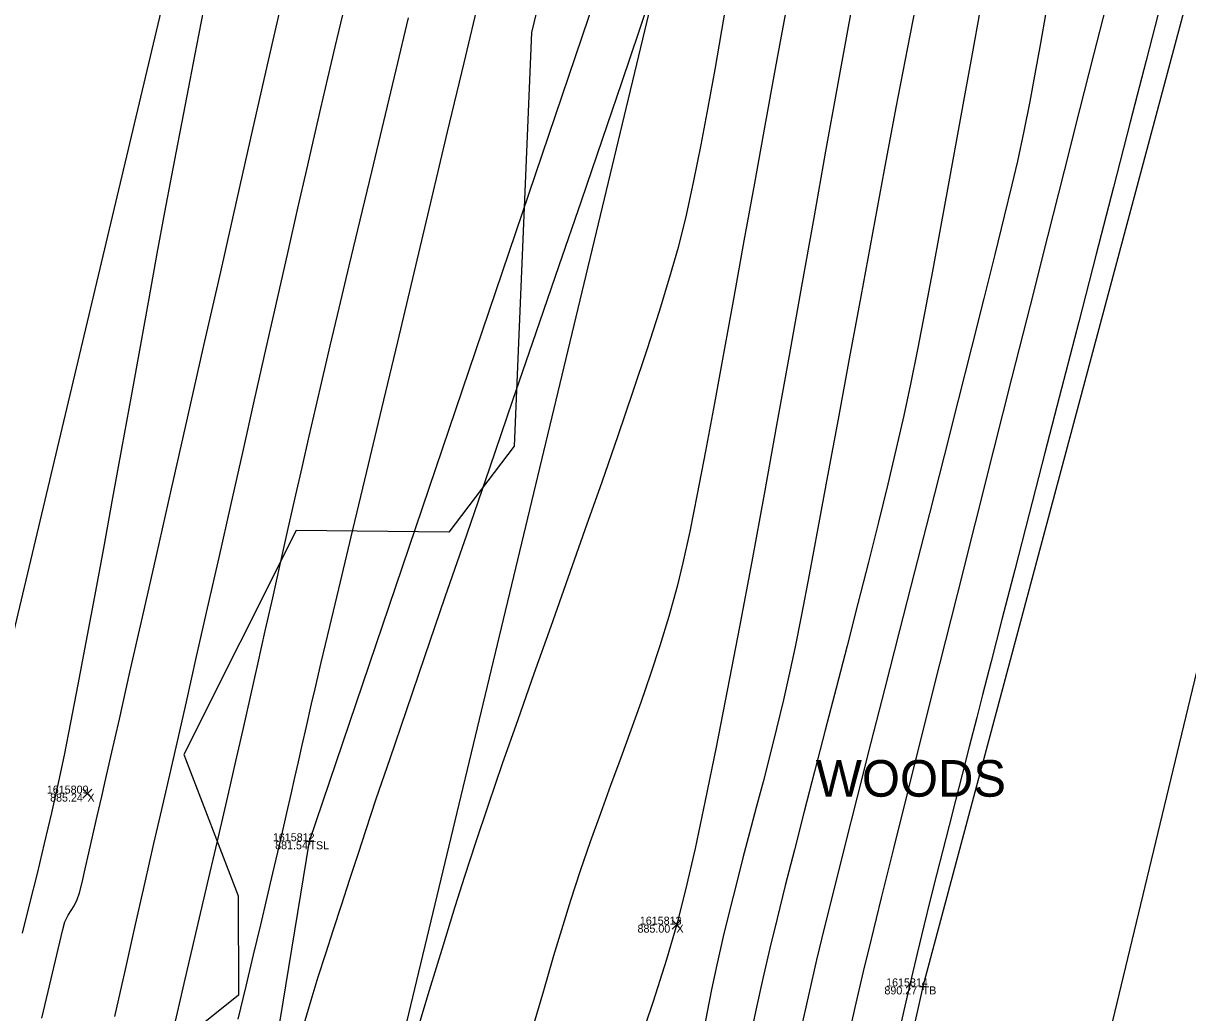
# Model space of a CAD drawing. Extents: x 1957117 to 1971063, y 701601 to 715861.
# Drawn here: x 1962959.5 to 1963010.4, y 704725.9 to 704769.1 of the extents above; entities that cross this region are included whole.
import ezdxf

# ---------------------------------------------------------------- set-up
doc = ezdxf.new("R2010")
doc.units = 0
for name, color, linetype in [('AP_X_Lights', 7, 'Continuous'), ('DT_X_Break_Line', 7, 'Continuous'), ('DT_X_Contour_Major', 7, 'Continuous'), ('DT_X_Contour_Minor', 7, 'Continuous'), ('DT_X_TIN_Hull', 7, 'Continuous'), ('GE_X_CL_20', 7, 'Continuous'), ('HY_X_Water_Edge', 7, 'Continuous'), ('PV_P_Drive', 7, 'Continuous'), ('PV_P_Shoulder', 7, 'Continuous'), ('RS_Raster1', 7, 'Continuous'), ('RW_X_Esmt_RR', 7, 'Continuous'), ('SC_Scratch1', 7, 'Continuous'), ('VG_X_Text', 7, 'Continuous'), ('VG_X_Tree_Line_Rt', 7, 'Continuous')]:
    doc.layers.add(name, color=color, linetype=linetype)

msp = doc.modelspace()

# ---------------------------------------------------------------- linework, layer by layer
at = {"layer": 'AP_X_Lights'}
for p, q in [((1962962.134, 704735.237), (1962962.522, 704735.627)), ((1962962.134, 704735.627), (1962962.522, 704735.237)), ((1962987.896, 704729.509), (1962988.284, 704729.899)), ((1962987.896, 704729.899), (1962988.284, 704729.509))]:
    msp.add_line(p, q, dxfattribs=at)
at = {"layer": 'DT_X_Break_Line'}
for points in [[(1962854.549, 704243.654), (1962868.069, 704295.231), (1962879.669, 704344.313), (1962892.757, 704392.318), (1962905.964, 704443.142), (1962917.718, 704492.375), (1962926.962, 704538.336), (1962936.778, 704587.265), (1962949.215, 704630.669), (1962963.968, 704683.754), (1962972.038, 704733.348), (1962988.206, 704780.999), (1962994.689, 704830.943), (1963004.932, 704879.138), (1963021.822, 704927.498), (1963031.944, 704976.286), (1963045.21, 705027.355), (1963059.618, 705072.384), (1963067.267, 705121.949)], [(1963081.686, 705067.168), (1963070.617, 705018.992), (1963060.629, 704969.66), (1963044.793, 704921.859), (1963033.624, 704869.219), (1963022.038, 704824.561), (1963012.554, 704778.141), (1962998.858, 704727.004), (1962987.967, 704677.611), (1962975.675, 704626.305), (1962966.447, 704580.213), (1962950.262, 704533.092), (1962939.515, 704481.257), (1962926.044, 704436.037), (1962917.68, 704386.811), (1962906.11, 704337.415), (1962892.064, 704289.931), (1962881.011, 704234.451)]]:
    msp.add_lwpolyline(points, dxfattribs=at)
at = {"layer": 'DT_X_Contour_Major'}
for points in [[(1962996.058, 704771.404), (1962995.601, 704768.948), (1962995.119, 704766.305), (1962994.614, 704763.511), (1962994.093, 704760.601), (1962993.558, 704757.611), (1962993.015, 704754.578), (1962992.468, 704751.537), (1962991.922, 704748.523), (1962991.38, 704745.574), (1962990.848, 704742.724), (1962990.329, 704740.01), (1962989.829, 704737.467), (1962989.352, 704735.131), (1962988.901, 704733.039), (1962988.483, 704731.225), (1962988.1, 704729.726), (1962987.648, 704728.176), (1962987.068, 704726.348), (1962986.373, 704724.273)], [(1962996.058, 704771.404), (1962995.601, 704768.948), (1962995.119, 704766.305), (1962994.614, 704763.511), (1962994.093, 704760.601), (1962993.558, 704757.611), (1962993.015, 704754.578), (1962992.468, 704751.537), (1962991.922, 704748.523), (1962991.38, 704745.574), (1962990.848, 704742.724), (1962990.329, 704740.01), (1962989.829, 704737.467), (1962989.352, 704735.131), (1962988.901, 704733.039), (1962988.483, 704731.225), (1962988.1, 704729.726), (1962987.648, 704728.176), (1962987.068, 704726.348), (1962986.373, 704724.273)], [(1962960.331, 704725.618), (1962960.736, 704727.33), (1962961.048, 704728.638), (1962961.256, 704729.491), (1962961.346, 704729.834), (1962961.48, 704730.115), (1962961.615, 704730.321), (1962961.751, 704730.528), (1962961.885, 704730.808), (1962961.975, 704731.096), (1962962.093, 704731.549), (1962962.233, 704732.138), (1962962.393, 704732.837), (1962962.569, 704733.615), (1962962.757, 704734.445), (1962962.953, 704735.298), (1962963.092, 704735.906), (1962963.354, 704737.058), (1962963.725, 704738.69), (1962964.19, 704740.739), (1962964.735, 704743.141), (1962965.346, 704745.834), (1962966.007, 704748.753), (1962966.706, 704751.836), (1962967.427, 704755.019), (1962968.157, 704758.238), (1962968.881, 704761.431), (1962969.584, 704764.534), (1962970.253, 704767.483), (1962970.872, 704770.216)], [(1962960.331, 704725.618), (1962960.736, 704727.33), (1962961.048, 704728.638), (1962961.256, 704729.491), (1962961.346, 704729.834), (1962961.48, 704730.115), (1962961.615, 704730.321), (1962961.751, 704730.528), (1962961.885, 704730.808), (1962961.975, 704731.096), (1962962.093, 704731.549), (1962962.233, 704732.138), (1962962.393, 704732.837), (1962962.569, 704733.615), (1962962.757, 704734.445), (1962962.953, 704735.298), (1962963.092, 704735.906), (1962963.354, 704737.058), (1962963.725, 704738.69), (1962964.19, 704740.739), (1962964.735, 704743.141), (1962965.346, 704745.834), (1962966.007, 704748.753), (1962966.706, 704751.836), (1962967.427, 704755.019), (1962968.157, 704758.238), (1962968.881, 704761.431), (1962969.584, 704764.534), (1962970.253, 704767.483), (1962970.872, 704770.216)], [(1963009.269, 704769.969), (1963008.626, 704767.475), (1963007.93, 704764.777), (1963007.197, 704761.935), (1963006.442, 704759.01), (1963005.681, 704756.06), (1963004.929, 704753.146), (1963004.202, 704750.327), (1963003.516, 704747.664), (1963002.885, 704745.215), (1963002.325, 704743.04), (1963001.851, 704741.2), (1963001.48, 704739.754), (1963001.226, 704738.762), (1963000.897, 704737.471), (1963000.588, 704736.267), (1963000.295, 704735.128), (1963000.013, 704734.033), (1962999.738, 704732.959), (1962999.466, 704731.884), (1962999.191, 704730.787), (1962998.908, 704729.646), (1962998.615, 704728.438), (1962998.305, 704727.143), (1962998.074, 704726.146), (1962997.727, 704724.617)], [(1963009.269, 704769.969), (1963008.626, 704767.475), (1963007.93, 704764.777), (1963007.197, 704761.935), (1963006.442, 704759.01), (1963005.681, 704756.06), (1963004.929, 704753.146), (1963004.202, 704750.327), (1963003.516, 704747.664), (1963002.885, 704745.215), (1963002.325, 704743.04), (1963001.851, 704741.2), (1963001.48, 704739.754), (1963001.226, 704738.762), (1963000.897, 704737.471), (1963000.588, 704736.267), (1963000.295, 704735.128), (1963000.013, 704734.033), (1962999.738, 704732.959), (1962999.466, 704731.884), (1962999.191, 704730.787), (1962998.908, 704729.646), (1962998.615, 704728.438), (1962998.305, 704727.143), (1962998.074, 704726.146), (1962997.727, 704724.617)], [(1962967.404, 704769.702), (1962967.098, 704768.133), (1962966.805, 704766.619), (1962966.525, 704765.174), (1962966.262, 704763.813), (1962966.002, 704762.451), (1962965.703, 704760.848), (1962965.371, 704759.042), (1962965.011, 704757.073), (1962964.631, 704754.981), (1962964.236, 704752.805), (1962963.833, 704750.584), (1962963.428, 704748.358), (1962963.027, 704746.167), (1962962.636, 704744.05), (1962962.262, 704742.046), (1962961.912, 704740.195), (1962961.59, 704738.536), (1962961.305, 704737.109), (1962961.061, 704735.954), (1962960.756, 704734.594), (1962960.444, 704733.258), (1962960.125, 704731.939), (1962959.8, 704730.634), (1962959.47, 704729.338)], [(1962967.404, 704769.702), (1962967.098, 704768.133), (1962966.805, 704766.619), (1962966.525, 704765.174), (1962966.262, 704763.813), (1962966.002, 704762.451), (1962965.703, 704760.848), (1962965.371, 704759.042), (1962965.011, 704757.073), (1962964.631, 704754.981), (1962964.236, 704752.805), (1962963.833, 704750.584), (1962963.428, 704748.358), (1962963.027, 704746.167), (1962962.636, 704744.05), (1962962.262, 704742.046), (1962961.912, 704740.195), (1962961.59, 704738.536), (1962961.305, 704737.109), (1962961.061, 704735.954), (1962960.756, 704734.594), (1962960.444, 704733.258), (1962960.125, 704731.939), (1962959.8, 704730.634), (1962959.47, 704729.338)]]:
    msp.add_lwpolyline(points, dxfattribs=at)
at = {"layer": 'DT_X_Contour_Minor'}
for points in [[(1962987.088, 704770.672), (1962986.44, 704768.74), (1962985.683, 704766.505), (1962984.836, 704764.018), (1962983.918, 704761.333), (1962982.948, 704758.502), (1962981.944, 704755.578), (1962980.924, 704752.615), (1962979.909, 704749.664), (1962978.916, 704746.779), (1962977.965, 704744.012), (1962977.074, 704741.417), (1962976.262, 704739.046), (1962975.547, 704736.952), (1962974.949, 704735.189), (1962974.486, 704733.808), (1962974.177, 704732.862), (1962973.796, 704731.673), (1962973.43, 704730.547), (1962973.078, 704729.47), (1962972.739, 704728.427), (1962972.412, 704727.404), (1962972.095, 704726.385), (1962971.788, 704725.357)], [(1962987.088, 704770.672), (1962986.44, 704768.74), (1962985.683, 704766.505), (1962984.836, 704764.018), (1962983.918, 704761.333), (1962982.948, 704758.502), (1962981.944, 704755.578), (1962980.924, 704752.615), (1962979.909, 704749.664), (1962978.916, 704746.779), (1962977.965, 704744.012), (1962977.074, 704741.417), (1962976.262, 704739.046), (1962975.547, 704736.952), (1962974.949, 704735.189), (1962974.486, 704733.808), (1962974.177, 704732.862), (1962973.796, 704731.673), (1962973.43, 704730.547), (1962973.078, 704729.47), (1962972.739, 704728.427), (1962972.412, 704727.404), (1962972.095, 704726.385), (1962971.788, 704725.357)], [(1962990.344, 704770.487), (1962990.056, 704768.783), (1962989.765, 704767.087), (1962989.467, 704765.416), (1962989.161, 704763.786), (1962988.842, 704762.212), (1962988.508, 704760.711), (1962988.157, 704759.299), (1962987.792, 704758.005), (1962987.334, 704756.506), (1962986.794, 704754.83), (1962986.186, 704753.008), (1962985.524, 704751.069), (1962984.82, 704749.043), (1962984.088, 704746.961), (1962983.342, 704744.85), (1962982.594, 704742.742), (1962981.858, 704740.666), (1962981.147, 704738.652), (1962980.474, 704736.73), (1962979.853, 704734.929), (1962979.296, 704733.278), (1962978.818, 704731.809), (1962978.4, 704730.479), (1962977.882, 704728.803), (1962977.277, 704726.828), (1962976.6, 704724.602)], [(1962990.344, 704770.487), (1962990.056, 704768.783), (1962989.765, 704767.087), (1962989.467, 704765.416), (1962989.161, 704763.786), (1962988.842, 704762.212), (1962988.508, 704760.711), (1962988.157, 704759.299), (1962987.792, 704758.005), (1962987.334, 704756.506), (1962986.794, 704754.83), (1962986.186, 704753.008), (1962985.524, 704751.069), (1962984.82, 704749.043), (1962984.088, 704746.961), (1962983.342, 704744.85), (1962982.594, 704742.742), (1962981.858, 704740.666), (1962981.147, 704738.652), (1962980.474, 704736.73), (1962979.853, 704734.929), (1962979.296, 704733.278), (1962978.818, 704731.809), (1962978.4, 704730.479), (1962977.882, 704728.803), (1962977.277, 704726.828), (1962976.6, 704724.602)], [(1962998.668, 704770.525), (1962998.19, 704768.05), (1962997.69, 704765.426), (1962997.178, 704762.703), (1962996.661, 704759.93), (1962996.146, 704757.156), (1962995.643, 704754.431), (1962995.157, 704751.803), (1962994.698, 704749.322), (1962994.273, 704747.038), (1962993.889, 704744.998), (1962993.555, 704743.253), (1962993.278, 704741.851), (1962993.066, 704740.842), (1962992.766, 704739.528), (1962992.468, 704738.283), (1962992.171, 704737.092), (1962991.876, 704735.944), (1962991.582, 704734.824), (1962991.289, 704733.72), (1962990.998, 704732.618), (1962990.709, 704731.504), (1962990.422, 704730.367), (1962990.136, 704729.191), (1962989.853, 704727.95), (1962989.624, 704726.864), (1962989.431, 704725.888), (1962989.258, 704724.98)], [(1962998.668, 704770.525), (1962998.19, 704768.05), (1962997.69, 704765.426), (1962997.178, 704762.703), (1962996.661, 704759.93), (1962996.146, 704757.156), (1962995.643, 704754.431), (1962995.157, 704751.803), (1962994.698, 704749.322), (1962994.273, 704747.038), (1962993.889, 704744.998), (1962993.555, 704743.253), (1962993.278, 704741.851), (1962993.066, 704740.842), (1962992.766, 704739.528), (1962992.468, 704738.283), (1962992.171, 704737.092), (1962991.876, 704735.944), (1962991.582, 704734.824), (1962991.289, 704733.72), (1962990.998, 704732.618), (1962990.709, 704731.504), (1962990.422, 704730.367), (1962990.136, 704729.191), (1962989.853, 704727.95), (1962989.624, 704726.864), (1962989.431, 704725.888), (1962989.258, 704724.98)], [(1962968.928, 704725.578), (1962969.269, 704727.012), (1962969.597, 704728.391), (1962969.906, 704729.693), (1962970.189, 704730.89), (1962970.441, 704731.959), (1962970.656, 704732.873), (1962970.828, 704733.608), (1962971.055, 704734.594), (1962971.242, 704735.414), (1962971.403, 704736.135), (1962971.556, 704736.823), (1962971.717, 704737.543), (1962971.904, 704738.364), (1962972.131, 704739.35), (1962972.287, 704740.012), (1962972.558, 704741.158), (1962972.933, 704742.734), (1962973.397, 704744.687), (1962973.939, 704746.961), (1962974.545, 704749.504), (1962975.202, 704752.26), (1962975.897, 704755.177), (1962976.618, 704758.201), (1962977.35, 704761.276), (1962978.082, 704764.351), (1962978.801, 704767.369), (1962979.493, 704770.278)], [(1962968.928, 704725.578), (1962969.269, 704727.012), (1962969.597, 704728.391), (1962969.906, 704729.693), (1962970.189, 704730.89), (1962970.441, 704731.959), (1962970.656, 704732.873), (1962970.828, 704733.608), (1962971.055, 704734.594), (1962971.242, 704735.414), (1962971.403, 704736.135), (1962971.556, 704736.823), (1962971.717, 704737.543), (1962971.904, 704738.364), (1962972.131, 704739.35), (1962972.287, 704740.012), (1962972.558, 704741.158), (1962972.933, 704742.734), (1962973.397, 704744.687), (1962973.939, 704746.961), (1962974.545, 704749.504), (1962975.202, 704752.26), (1962975.897, 704755.177), (1962976.618, 704758.201), (1962977.35, 704761.276), (1962978.082, 704764.351), (1962978.801, 704767.369), (1962979.493, 704770.278)], [(1962963.529, 704725.692), (1962963.99, 704727.737), (1962964.434, 704729.708), (1962964.853, 704731.562), (1962965.237, 704733.252), (1962965.578, 704734.735), (1962965.885, 704736.066), (1962966.248, 704737.648), (1962966.657, 704739.444), (1962967.105, 704741.418), (1962967.583, 704743.531), (1962968.084, 704745.747), (1962968.599, 704748.029), (1962969.121, 704750.339), (1962969.64, 704752.64), (1962970.149, 704754.896), (1962970.64, 704757.069), (1962971.104, 704759.121), (1962971.534, 704761.017), (1962971.921, 704762.718), (1962972.257, 704764.188), (1962972.534, 704765.389), (1962972.843, 704766.71), (1962973.164, 704768.073), (1962973.496, 704769.469)], [(1962963.529, 704725.692), (1962963.99, 704727.737), (1962964.434, 704729.708), (1962964.853, 704731.562), (1962965.237, 704733.252), (1962965.578, 704734.735), (1962965.885, 704736.066), (1962966.248, 704737.648), (1962966.657, 704739.444), (1962967.105, 704741.418), (1962967.583, 704743.531), (1962968.084, 704745.747), (1962968.599, 704748.029), (1962969.121, 704750.339), (1962969.64, 704752.64), (1962970.149, 704754.896), (1962970.64, 704757.069), (1962971.104, 704759.121), (1962971.534, 704761.017), (1962971.921, 704762.718), (1962972.257, 704764.188), (1962972.534, 704765.389), (1962972.843, 704766.71), (1962973.164, 704768.073), (1962973.496, 704769.469)], [(1962966.023, 704724.792), (1962966.61, 704727.314), (1962967.134, 704729.568), (1962967.582, 704731.498), (1962967.943, 704733.051), (1962968.203, 704734.171), (1962968.507, 704735.489), (1962968.819, 704736.848), (1962969.135, 704738.24), (1962969.456, 704739.659), (1962969.779, 704741.096), (1962970.105, 704742.544), (1962970.431, 704743.996), (1962970.756, 704745.445), (1962971.08, 704746.882), (1962971.401, 704748.301), (1962971.717, 704749.693), (1962972.028, 704751.052), (1962972.333, 704752.37), (1962972.611, 704753.558), (1962972.951, 704754.998), (1962973.344, 704756.657), (1962973.783, 704758.501), (1962974.26, 704760.497), (1962974.765, 704762.611), (1962975.292, 704764.812), (1962975.831, 704767.066), (1962976.375, 704769.339)], [(1962966.023, 704724.792), (1962966.61, 704727.314), (1962967.134, 704729.568), (1962967.582, 704731.498), (1962967.943, 704733.051), (1962968.203, 704734.171), (1962968.507, 704735.489), (1962968.819, 704736.848), (1962969.135, 704738.24), (1962969.456, 704739.659), (1962969.779, 704741.096), (1962970.105, 704742.544), (1962970.431, 704743.996), (1962970.756, 704745.445), (1962971.08, 704746.882), (1962971.401, 704748.301), (1962971.717, 704749.693), (1962972.028, 704751.052), (1962972.333, 704752.37), (1962972.611, 704753.558), (1962972.951, 704754.998), (1962973.344, 704756.657), (1962973.783, 704758.501), (1962974.26, 704760.497), (1962974.765, 704762.611), (1962975.292, 704764.812), (1962975.831, 704767.066), (1962976.375, 704769.339)], [(1962992.856, 704769.56), (1962992.407, 704767.131), (1962991.952, 704764.635), (1962991.496, 704762.11), (1962991.043, 704759.594), (1962990.598, 704757.127), (1962990.167, 704754.747), (1962989.753, 704752.494), (1962989.363, 704750.407), (1962988.999, 704748.523), (1962988.669, 704746.883), (1962988.375, 704745.524), (1962988.123, 704744.487), (1962987.757, 704743.172), (1962987.368, 704741.895), (1962986.96, 704740.646), (1962986.536, 704739.418), (1962986.101, 704738.204), (1962985.659, 704736.995), (1962985.212, 704735.783), (1962984.765, 704734.561), (1962984.321, 704733.321), (1962983.884, 704732.055), (1962983.459, 704730.755), (1962983.119, 704729.661), (1962982.719, 704728.336), (1962982.269, 704726.815), (1962981.776, 704725.13)], [(1962992.856, 704769.56), (1962992.407, 704767.131), (1962991.952, 704764.635), (1962991.496, 704762.11), (1962991.043, 704759.594), (1962990.598, 704757.127), (1962990.167, 704754.747), (1962989.753, 704752.494), (1962989.363, 704750.407), (1962988.999, 704748.523), (1962988.669, 704746.883), (1962988.375, 704745.524), (1962988.123, 704744.487), (1962987.757, 704743.172), (1962987.368, 704741.895), (1962986.96, 704740.646), (1962986.536, 704739.418), (1962986.101, 704738.204), (1962985.659, 704736.995), (1962985.212, 704735.783), (1962984.765, 704734.561), (1962984.321, 704733.321), (1962983.884, 704732.055), (1962983.459, 704730.755), (1962983.119, 704729.661), (1962982.719, 704728.336), (1962982.269, 704726.815), (1962981.776, 704725.13)], [(1963001.359, 704769.632), (1963001.016, 704767.773), (1963000.669, 704765.865), (1963000.319, 704763.934), (1962999.971, 704762.006), (1962999.625, 704760.107), (1962999.285, 704758.263), (1962998.953, 704756.5), (1962998.632, 704754.844), (1962998.324, 704753.322), (1962998.032, 704751.959), (1962997.705, 704750.522), (1962997.333, 704748.958), (1962996.925, 704747.291), (1962996.488, 704745.544), (1962996.029, 704743.738), (1962995.556, 704741.898), (1962995.078, 704740.047), (1962994.6, 704738.206), (1962994.131, 704736.399), (1962993.678, 704734.649), (1962993.249, 704732.98), (1962992.851, 704731.413), (1962992.491, 704729.971), (1962992.178, 704728.679), (1962991.871, 704727.348), (1962991.568, 704725.967), (1962991.268, 704724.547)], [(1963001.359, 704769.632), (1963001.016, 704767.773), (1963000.669, 704765.865), (1963000.319, 704763.934), (1962999.971, 704762.006), (1962999.625, 704760.107), (1962999.285, 704758.263), (1962998.953, 704756.5), (1962998.632, 704754.844), (1962998.324, 704753.322), (1962998.032, 704751.959), (1962997.705, 704750.522), (1962997.333, 704748.958), (1962996.925, 704747.291), (1962996.488, 704745.544), (1962996.029, 704743.738), (1962995.556, 704741.898), (1962995.078, 704740.047), (1962994.6, 704738.206), (1962994.131, 704736.399), (1962993.678, 704734.649), (1962993.249, 704732.98), (1962992.851, 704731.413), (1962992.491, 704729.971), (1962992.178, 704728.679), (1962991.871, 704727.348), (1962991.568, 704725.967), (1962991.268, 704724.547)], [(1963004.224, 704769.486), (1963004.005, 704768.234), (1963003.777, 704766.966), (1963003.537, 704765.683), (1963003.279, 704764.385), (1963002.999, 704763.075), (1963002.76, 704762.04), (1963002.428, 704760.666), (1963002.017, 704758.996), (1963001.536, 704757.072), (1963000.997, 704754.936), (1963000.412, 704752.631), (1962999.793, 704750.199), (1962999.15, 704747.682), (1962998.496, 704745.122), (1962997.841, 704742.561), (1962997.198, 704740.042), (1962996.577, 704737.606), (1962995.991, 704735.297), (1962995.451, 704733.157), (1962994.968, 704731.227), (1962994.554, 704729.549), (1962994.22, 704728.167), (1962993.876, 704726.681), (1962993.504, 704725.01)], [(1963004.224, 704769.486), (1963004.005, 704768.234), (1963003.777, 704766.966), (1963003.537, 704765.683), (1963003.279, 704764.385), (1963002.999, 704763.075), (1963002.76, 704762.04), (1963002.428, 704760.666), (1963002.017, 704758.996), (1963001.536, 704757.072), (1963000.997, 704754.936), (1963000.412, 704752.631), (1962999.793, 704750.199), (1962999.15, 704747.682), (1962998.496, 704745.122), (1962997.841, 704742.561), (1962997.198, 704740.042), (1962996.577, 704737.606), (1962995.991, 704735.297), (1962995.451, 704733.157), (1962994.968, 704731.227), (1962994.554, 704729.549), (1962994.22, 704728.167), (1962993.876, 704726.681), (1962993.504, 704725.01)], [(1963006.865, 704769.826), (1963006.332, 704767.722), (1963005.721, 704765.314), (1963005.046, 704762.65), (1963004.319, 704759.782), (1963003.553, 704756.76), (1963002.761, 704753.633), (1963001.957, 704750.452), (1963001.152, 704747.267), (1963000.36, 704744.128), (1962999.594, 704741.085), (1962998.867, 704738.189), (1962998.191, 704735.489), (1962997.58, 704733.035), (1962997.046, 704730.878), (1962996.603, 704729.068), (1962996.262, 704727.655), (1962995.896, 704726.08), (1962995.472, 704724.206)], [(1963006.865, 704769.826), (1963006.332, 704767.722), (1963005.721, 704765.314), (1963005.046, 704762.65), (1963004.319, 704759.782), (1963003.553, 704756.76), (1963002.761, 704753.633), (1963001.957, 704750.452), (1963001.152, 704747.267), (1963000.36, 704744.128), (1962999.594, 704741.085), (1962998.867, 704738.189), (1962998.191, 704735.489), (1962997.58, 704733.035), (1962997.046, 704730.878), (1962996.603, 704729.068), (1962996.262, 704727.655), (1962995.896, 704726.08), (1962995.472, 704724.206)]]:
    msp.add_lwpolyline(points, dxfattribs=at)
at = {"layer": 'DT_X_TIN_Hull'}
msp.add_lwpolyline([(1963062.2, 705175.46), (1963037.999, 705077.244), (1963026.56, 705028.621), (1963015.244, 704980.352), (1962992.578, 704882.771), (1962981.085, 704833.91), (1962969.384, 704785.804), (1962957.851, 704737.276), (1962945.67, 704688.173), (1962933.954, 704639.432), (1962922.363, 704591.169), (1962899.093, 704494.258), (1962887.945, 704444.945), (1962875.826, 704396.455), (1962864.548, 704347.909), (1962854.544, 704302.816), (1962839.463, 704247.251)], dxfattribs=at)
at = {"layer": 'GE_X_CL_20'}
msp.add_lwpolyline([(1963418.3, 706437.397), (1962895.621, 704261.062)], dxfattribs=at)
at = {"layer": 'HY_X_Water_Edge'}
msp.add_spline([(1963191.723, 701994.048), (1963062.047, 702441.167), (1962863.491, 703169.356), (1962827.53, 703438.691), (1962823.213, 703537.412), (1962817.962, 703593.874), (1962817.97, 703697.316), (1962828.582, 703804.235), (1962836.461, 703844.734), (1962850.687, 703896.004), (1962867.251, 703938.846), (1962873.848, 703992.355), (1962884.135, 704091.371), (1962891.241, 704140.854), (1962897.382, 704180.529), (1962905.467, 704230.979), (1962943.949, 704328.022), (1962948.537, 704378.842), (1962964.114, 704426.264), (1963004.885, 704570.73), (1963042.054, 704716.522), (1963062.038, 704814.417), (1963072.171, 704860.237), (1963090.023, 704956.798), (1963107.066, 705031.783), (1963133.773, 705105.742), (1963148.685, 705206.74), (1963175.48, 705301.059), (1963191.635, 705353.417), (1963210.988, 705447.286), (1963219.532, 705497.27), (1963230.124, 705549.475), (1963251.052, 705591.159), (1963275.289, 705693.429), (1963292.982, 705784.032), (1963302.841, 705839.645), (1963335.126, 705936.766), (1963359.752, 706046.75), (1963389.133, 706177.299), (1963417.827, 706273.456), (1963475.868, 706451.902), (1963533.782, 706640.53), (1963553.86, 706696.984), (1963580.184, 706715.425), (1963609.172, 706718.73), (1963617.062, 706714.691), (1963619.447, 706694.678), (1963564.282, 706533.07), (1963531.853, 706395.229), (1963434.4, 706006.96), (1963354.09, 705679.186), (1963237.513, 705206.07), (1963167.369, 704892.962), (1963059.145, 704434.176), (1962907.914, 703908.742), (1962877.458, 703703.326), (1962898.357, 703412.121), (1962942.65, 703052.267), (1963048.963, 702674.866), (1963191.468, 702189.666), (1963245.396, 702019.832)], degree=3, dxfattribs=at)
at = {"layer": 'PV_P_Drive'}
for p, q in [((1962971.892, 704733.348), (1962972.184, 704733.348)), ((1962972.038, 704733.494), (1962972.038, 704733.202)), ((1962972.038, 704733.348), (1962972.038, 704733.348)), ((1962998.858, 704727.15), (1962998.858, 704726.858)), ((1962998.712, 704727.004), (1962999.004, 704727.004)), ((1962998.858, 704727.004), (1962998.858, 704727.004))]:
    msp.add_line(p, q, dxfattribs=at)
at = {"layer": 'RW_X_Esmt_RR'}
msp.add_lwpolyline([(1962866.45, 704268.068), (1963123.345, 705337.727), (1963135.496, 705336.937), (1963400.797, 706441.601)], dxfattribs=at)
at = {"layer": 'VG_X_Tree_Line_Rt'}
msp.add_lwpolyline([(1962986.237, 704787.296), (1962981.745, 704768.701), (1962980.999, 704750.624), (1962978.13, 704746.854), (1962971.461, 704746.926), (1962966.551, 704737.148), (1962968.927, 704730.966), (1962968.939, 704726.627), (1962964.184, 704722.821), (1962959.744, 704715.96), (1962961.918, 704707.89), (1962967.024, 704704.665), (1962971.423, 704700.785), (1962967.465, 704693.674), (1962959.916, 704673.133)], dxfattribs=at)

# ---------------------------------------------------------------- texts
at = {"layer": 'PV_P_Shoulder'}
for s, p in [('885.24', (1962960.697, 704735.082)), ('881.54', (1962970.539, 704732.998)), ('885.00', (1962986.387, 704729.354)), ('890.27', (1962997.185, 704726.654))]:
    msp.add_text(s, height=0.35, dxfattribs=at).set_placement(p)
at = {"layer": 'RS_Raster1'}
for s, p in [('1615809', (1962960.554, 704735.432)), ('1615812', (1962970.44, 704733.348)), ('1615813', (1962986.489, 704729.704)), ('1615814', (1962997.26, 704727.004))]:
    msp.add_text(s, height=0.35, dxfattribs=at).set_placement(p)
at = {"layer": 'SC_Scratch1'}
for s, p in [('X', (1962962.328, 704735.082)), ('TSL', (1962972.038, 704732.998)), ('X', (1962988.09, 704729.354)), ('TB', (1962998.858, 704726.654))]:
    msp.add_text(s, height=0.35, dxfattribs=at).set_placement(p)
at = {"layer": 'VG_X_Text'}
msp.add_text('WOODS', height=1.6, dxfattribs=at).set_placement((1962994.181, 704735.297))

doc.saveas('drawing.dxf')
